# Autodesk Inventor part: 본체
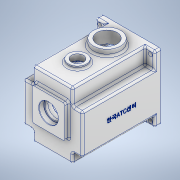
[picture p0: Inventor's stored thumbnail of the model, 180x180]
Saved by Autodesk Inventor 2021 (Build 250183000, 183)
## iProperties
Created: 2022-08
Part Number: 본체
Material: 알루미늄 6061
Document SubType Name: Modeling
Designer: Owner
Mass: 1403.62 g
Surface Area: 1171.87 cm^2
Volume: 519.86 cm^3
Density: 2.7 g/cm^3
Appearance: 알루미늄 - 평지
Author: Owner
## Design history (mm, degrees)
sketch "스케치1"
  geometry: L1 (-49, 55)-(49, 55); L2 (49, 55)-(49, -55); L3 (49, -55)-(-49, -55); L4 (-49, -55)-(-49, 55); L5 (-49, 55)-(49, -55); L6 (49, 55)-(-49, -55); 1 further point
  constraints: 12 end point, 2 midpoint, 2 parallel, 1 horizontal, 1 perpendicular
  dimensions: "d0" = 98 distance of L2.end L3.end; "d1" = 110 distance of L1.end L2.end
extrude "돌출1" new body sketch "스케치1" stored distance "d2" = 130; taper "d3" = 0 deg
sketch "스케치2"
  geometry: L1 (-27, 33)-(27, 33); L2 (27, 33)-(27, -21); L3 (27, -21)-(-27, -21); L4 (-27, -21)-(-27, 33); L5 (-27, 33)-(27, -21); L6 (27, 33)-(-27, -21); L7 (49, -55)-(49, 55) reference; L8 (-49, -55)-(49, -55) reference; 4 further points
  constraints: 12 end point, 4 midpoint, 2 parallel, 1 horizontal, 1 perpendicular, 1 vertical alignment
  dimensions: "d4" = 54 distance of L2.end L3.end; "d5" = 54 distance of L1.end L2.end; "d131" = 61 vertical distance of point (0, -55) point (27, 6)
extrude "돌출2" join sketch "스케치2" distance "d6" = 7; taper "d7" = 0 deg
sketch "스케치3"
  geometry: L1 (49, 55)-(-49, 55) reference; L2 (-49, 55)-(-33, 55); L3 (-33, 55)-(-33, 28); L4 (-33, 28)-(-49, 28); L5 (-49, 28)-(-49, 55); L6 (49, 55)-(33, 55); L7 (33, 55)-(33, 28); L8 (33, 28)-(49, 28); L9 (49, 28)-(49, 55); L10 (-49, 55)-(-49, -55) reference; L11 (-49, -55)-(-33, -55); L12 (-33, -55)-(-33, -38); L13 (-33, -38)-(-49, -38); L14 (-49, -38)-(-49, -55); L15 (49, -55)-(49, 55) reference; L16 (49, -55)-(33, -55); L17 (33, -55)-(33, -38); L18 (33, -38)-(49, -38); L19 (49, -38)-(49, -55); 5 further points
  constraints: 32 end point, 8 parallel, 4 horizontal, 4 perpendicular, 2 point on line
  dimensions: "d8" = 16 distance between parallel lines of L5 L3; "d9" = 16 distance between parallel lines of L9 L7; "d10" = 27 distance between parallel lines of L4 L1; "d11" = 17 distance between parallel lines of L11 L13; "d12" = 16 distance between parallel lines of L10 L12; "d13" = 16 distance between parallel lines of L15 L17
extrude "돌출3" cut sketch "스케치3" distance "d14" = 120; taper "d15" = 0 deg
sketch "스케치4"
  geometry: L1 (0, 0)-(98, 0) reference; C1 r 15 at (49, -89); 1 further point
  constraints: 1 centre point, 1 vertical alignment
  dimensions: "d16" = 30 diameter of C1; "d17" = 89 distance from line of L1 C1.centre
extrude "돌출4" join sketch "스케치4" distance "d18" = 5; taper "d19" = 0 deg
sketch "스케치5"
  geometry: L1 (0, 0)-(98, 0) reference; C1 r 22.5 at (49, -40); 1 further point
  constraints: 1 centre point, 1 vertical alignment
  dimensions: "d20" = 45 diameter of C1; "d21" = 40 distance from line of L1 C1.centre
extrude "돌출5" join sketch "스케치5" distance "d22" = 10; taper "d23" = 0 deg
sketch "스케치6"
  geometry: L1 (-26, 48)-(26, 48); L2 (26, 48)-(26, 20.088); L3 (26, 20.088)-(-26, 20.088); L4 (-26, 20.088)-(-26, 48); L5 (49, 55)-(-49, 55) reference; L6 (-49, -55)-(49, -55) reference; C1 r 45 at (0, -5); 4 further points
  constraints: 8 end point, 2 parallel, 2 vertical alignment, 1 centre point, 1 horizontal, 1 midpoint, 1 perpendicular
  dimensions: "d25" = 52 distance of L2.end L3.end; "d26" = 7 distance between parallel lines of L5 L1; "d27" = 50 distance from line of L6 C1.centre; "d28" = 90 diameter of C1
extrude "돌출6" cut sketch "스케치6" distance "d29" = 9; taper "d30" = 0 deg
sketch "스케치7"
  geometry: L1 (-23, 45)-(23, 45); L2 (23, 45)-(23, 8.693); L3 (23, 8.693)-(-23, 8.693); L4 (-23, 8.693)-(-23, 45); L5 (49, 55)-(-49, 55) reference; C1 r 42 at (0, -5); A1 r 45 centre (0, -5) between (-26, 31.729) and (26, 31.729) reference; 4 further points
  constraints: 8 end point, 2 parallel, 1 centre point, 1 concentric, 1 horizontal, 1 midpoint, 1 perpendicular, 1 vertical alignment
  dimensions: "d31" = 10 distance between parallel lines of L5 L1; "d32" = 46 distance between parallel lines of L4 L2; "d33" = 84 diameter of C1
extrude "돌출7" cut sketch "스케치7" distance "d34" = 112; taper "d35" = 0 deg
sketch "스케치11"
  geometry: A1 r 15 centre (0, -25) between (-8.978, -12.984) and (8.978, -12.984); A2 r 21 centre (0, 6) between (8.978, -12.984) and (-8.978, -12.984); A3 r 42 centre (0, -5) between (-23, 30.143) and (23, 30.143) reference; 1 further point
  constraints: 4 point on circle, 2 centre point, 2 vertical alignment
  dimensions: "d47" = 30 diameter of A1; "d49" = 42 diameter of A2; "d126" = 11 distance of A2.centre A3.centre; "d127" = 20 distance of A1.centre A3.centre
extrude "돌출11" join sketch "스케치11" distance "d51" = 7; taper "d52" = 0 deg
sketch "스케치12"
  geometry: C1 r 17.5 at (0, 6); A1 r 21 centre (0, 6) between (8.978, -12.984) and (-8.978, -12.984) reference; 1 further point
  constraints: 1 centre point, 1 concentric
  dimensions: "d53" = 35 diameter of C1
extrude "돌출12" cut sketch "스케치12" distance "d54" = 10; taper "d55" = 0 deg
sketch "스케치14"
  geometry: C1 r 11 at (0, -25); A1 r 15 centre (0, -25) between (-8.978, -12.984) and (8.978, -12.984) reference; 1 further point
  constraints: 1 centre point, 1 concentric
  dimensions: "d59" = 22 diameter of C1
extrude "돌출14" cut sketch "스케치14" distance "d60" = 7; taper "d61" = 0 deg
sketch "스케치15"
  geometry: C1 r 9.5 at (0, 0); C2 r 11 at (0, 0) reference; 1 further point
  constraints: 1 centre point, 1 concentric
  dimensions: "d62" = 19 diameter of C1
extrude "돌출15" cut sketch "스케치15" distance "d63" = 3; taper "d64" = 0 deg
sketch "스케치16"
  geometry: L1 (-35.778, -1.006)-(-41.81, -1.006); L2 (-41.809, -9)-(-35.778, -9); L3 (-35.778, -9)-(-35.778, -8.994); L4 (36.222, -1.006)-(41.81, -1.006); L5 (41.809, -9)-(36.222, -9); L6 (36.222, -9)-(36.222, -8.994); A1 r 36 centre (0, -5) between (35.778, -1.006) and (35.778, -8.994); A2 r 42 centre (0, -5) between (-23, 30.143) and (23, 30.143) reference; A3 r 4 centre (-36, -5) between (-36, -9) and (-36.222, -1.006); A4 r 4 centre (36, -5) between (36.222, -1.006) and (36.222, -8.994); 1 further point
  constraints: 17 point on circle, 12 end point, 3 centre point, 3 point on line, 2 horizontal, 2 horizontal alignment, 2 parallel, 2 tangent, 1 concentric
  dimensions: "d65" = 72 diameter of A1; "d66" = 8 diameter of A4; "d67" = 8 diameter of A3
extrude "돌출16" join sketch "스케치16" stored distance "d68" = 8 (= d66); taper "d69" = 0 deg
sketch "스케치17"
  geometry: C1 r 10 at (0, 0); 1 further point
  constraints: 1 centre point
  dimensions: "d70" = 20 diameter of C1
sketch "스케치18"
  geometry: C1 r 15 at (23, 80) reference; C2 r 15 at (23, 80); 1 further point
  constraints: 1 centre point, 1 coincident
  dimensions: "d71" = 30 diameter of C2
extrude "돌출17" cut sketch "스케치18" distance "d72" = 5; taper "d73" = 0 deg
extrude "돌출18" cut sketch "스케치17" stored distance "d74" = 5; taper "d75" = 0 deg
sketch "스케치19"
  geometry: C1 r 22.5 at (0, 0) reference; 2 further points
  constraints: 1 coincident
hole "구멍1" sketch "스케치19" at (0, 0) diameter "d76" = 33.376; stored, may be unused: countersink angle "d80" = 90 deg, drill point angle "d82" = 118 deg; dims "d77" = 70, "d78" = 4, "d79" = 2, "d81" = 77.3
chamfer "모따기1" distance "d83" = 1; stored, may be unused: second distance "d84" = 2, angle "d85" = 45 deg
fillet "모깎기1" dims "d86" = 3
fillet "모깎기2" dims "d87" = 3
sketch "스케치20"
  geometry: L1 (-130, 104)-(-130, 83) reference; L2 (-7, 107)-(-127, 107) reference; 3 further points
  constraints: 1 other
  dimensions: "d90" = 65 distance from line of L1 point (-65, 47); "d91" = 60 distance from line of L2 point (-65, 47)
feature "엠보싱1" sketch "스케치20" dims "d92" = 0.5, "d93" = 0
sketch "스케치21"
  geometry: L1 (-30, 55)-(-46, 55) reference; L2 (-49, 52)-(-49, 25) reference; L3 (-46, 55)-(46, 55) reference; L4 (49, 25)-(49, 52) reference; L5 (49, 52)-(49, -52) reference; L6 (30, -55)-(46, -55) reference; L7 (-49, -52)-(-49, 52) reference; L8 (46, -55)-(-46, -55) reference; C1 r 3.5 at (-42, 48); C2 r 3.5 at (42, 48); C3 r 3.5 at (42, -48); C4 r 3.5 at (-42, -48); 1 further point
  constraints: 4 centre point
  dimensions: "d94" = 7 diameter of C4; "d95" = 7 diameter of C1; "d96" = 7 diameter of C2; "d97" = 7 diameter of C3; "d98" = 7 distance from line of C1.centre L1; "d99" = 7 distance from line of L2 C1.centre; "d100" = 7 distance from line of L3 C2.centre; "d101" = 7 distance from line of L4 C2.centre; "d102" = 7 distance from line of L5 C3.centre; "d103" = 7 distance from line of L6 C3.centre; "d104" = 7 distance from line of L7 C4.centre; "d105" = 7 distance from line of L8 C4.centre
extrude "돌출19" cut sketch "스케치21" stored distance "d106" = 7 (= d94); taper "d107" = 0 deg
fillet "모깎기5" dims "d108" = 6
fillet "모깎기6" dims "d109" = 3
fillet "모깎기7" dims "d110" = 3
fillet "모깎기8" dims "d111" = 3
fillet "모깎기9" dims "d112" = 3
sketch "스케치22"
  geometry: A1 r 4 centre (-36, -5) between (-36, -9) and (-35.778, -1.006) reference; A2 r 4 centre (36, -5) between (36.222, -1.006) and (36.222, -8.994) reference; 3 further points
  constraints: 2 coincident
hole "구멍2" sketch "스케치22" at (-36, -5), (36, -5) diameter "d113" = 3.242; stored, may be unused: countersink angle "d117" = 90 deg, drill point angle "d119" = 118 deg; dims "d114" = 7, "d115" = 4, "d116" = 2, "d118" = 9
fillet "모깎기10" dims "d120" = 3
fillet "모깎기11" dims "d121" = 6
fillet "모깎기12" dims "d122" = 0.3
sketch "스케치24"
  geometry: L1 (-30, -55)-(30, -55) reference; C1 r 16 at (0, 6); 1 further point
  constraints: 1 centre point, 1 vertical alignment
  dimensions: "d133" = 61 distance from line of L1 C1.centre; "d134" = 32 diameter of C1
extrude "돌출21" cut sketch "스케치24" distance "d135" = 8.3; taper "d136" = 0 deg
sketch "스케치25"
  geometry: L1 (-30, -61)-(30, -61) reference; C1 r 14 at (0, 0); 1 further point
  constraints: 1 centre point, 1 vertical alignment
  dimensions: "d137" = 61 distance from line of L1 C1.centre; "d138" = 28 diameter of C1
extrude "돌출22" cut sketch "스케치25" distance "d139" = 8.3; taper "d140" = 0 deg
chamfer "모따기3" distance "d141" = 0.8; stored, may be unused: second distance "d142" = 2, angle "d143" = 30 deg
fillet "모깎기13" dims "d144" = 3
fillet "모깎기14" dims "d145" = 0.3
chamfer "모따기4" distance "d147" = 1; stored, may be unused: second distance "d148" = 2, angle "d149" = 60 deg
fillet "모깎기16" dims "d150" = 0.3
node "솔리드1"
feature "A9D066F2-1C7D-4E18-AEED-F7BC21143FA4" dims "d113" = 3.242, "d114" = 7, "d115" = 4, "d116" = 2, "d117" = 90 deg, "d118" = 9, "d119" = 118 deg
